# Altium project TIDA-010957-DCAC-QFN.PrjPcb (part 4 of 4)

## Sheet TIDA-010957-DCAC-Power-Tree.SchDoc
size 558 x 431 mm; Date: Not shown in title block; ApprovedBy: Not shown in title block; CheckedBy: Not shown in title block; Author: Not shown in title block; CompanyName: Not shown in title block; Engineer: Not shown in title block; Organization: Not shown in title block; Address1: Not shown in title block; Address2: Not shown in title block; Address3: Not shown in title block; Address4: Not shown in title block; DocumentNumber: 1; Revision: Use project parameter SCH_Rev; SheetNumber: 11; SheetTotal: 12; PageSetup: Record=PageOptions¦CenterHorizontal=True¦CenterVertical=True¦PrintScale=1.00¦XCorrection=1.00¦YCorrection=1.00¦PrintKind=0¦BorderSize=5000000¦LeftOffset=0¦BottomOffset=0¦Orientation=2¦PaperLength=1000¦PaperWidth=1000¦Scale=100¦PaperSource=15¦PrintQuality=600¦MediaType=1¦DitherType=10¦PaperKind=Letter¦PrintScaleMode=1
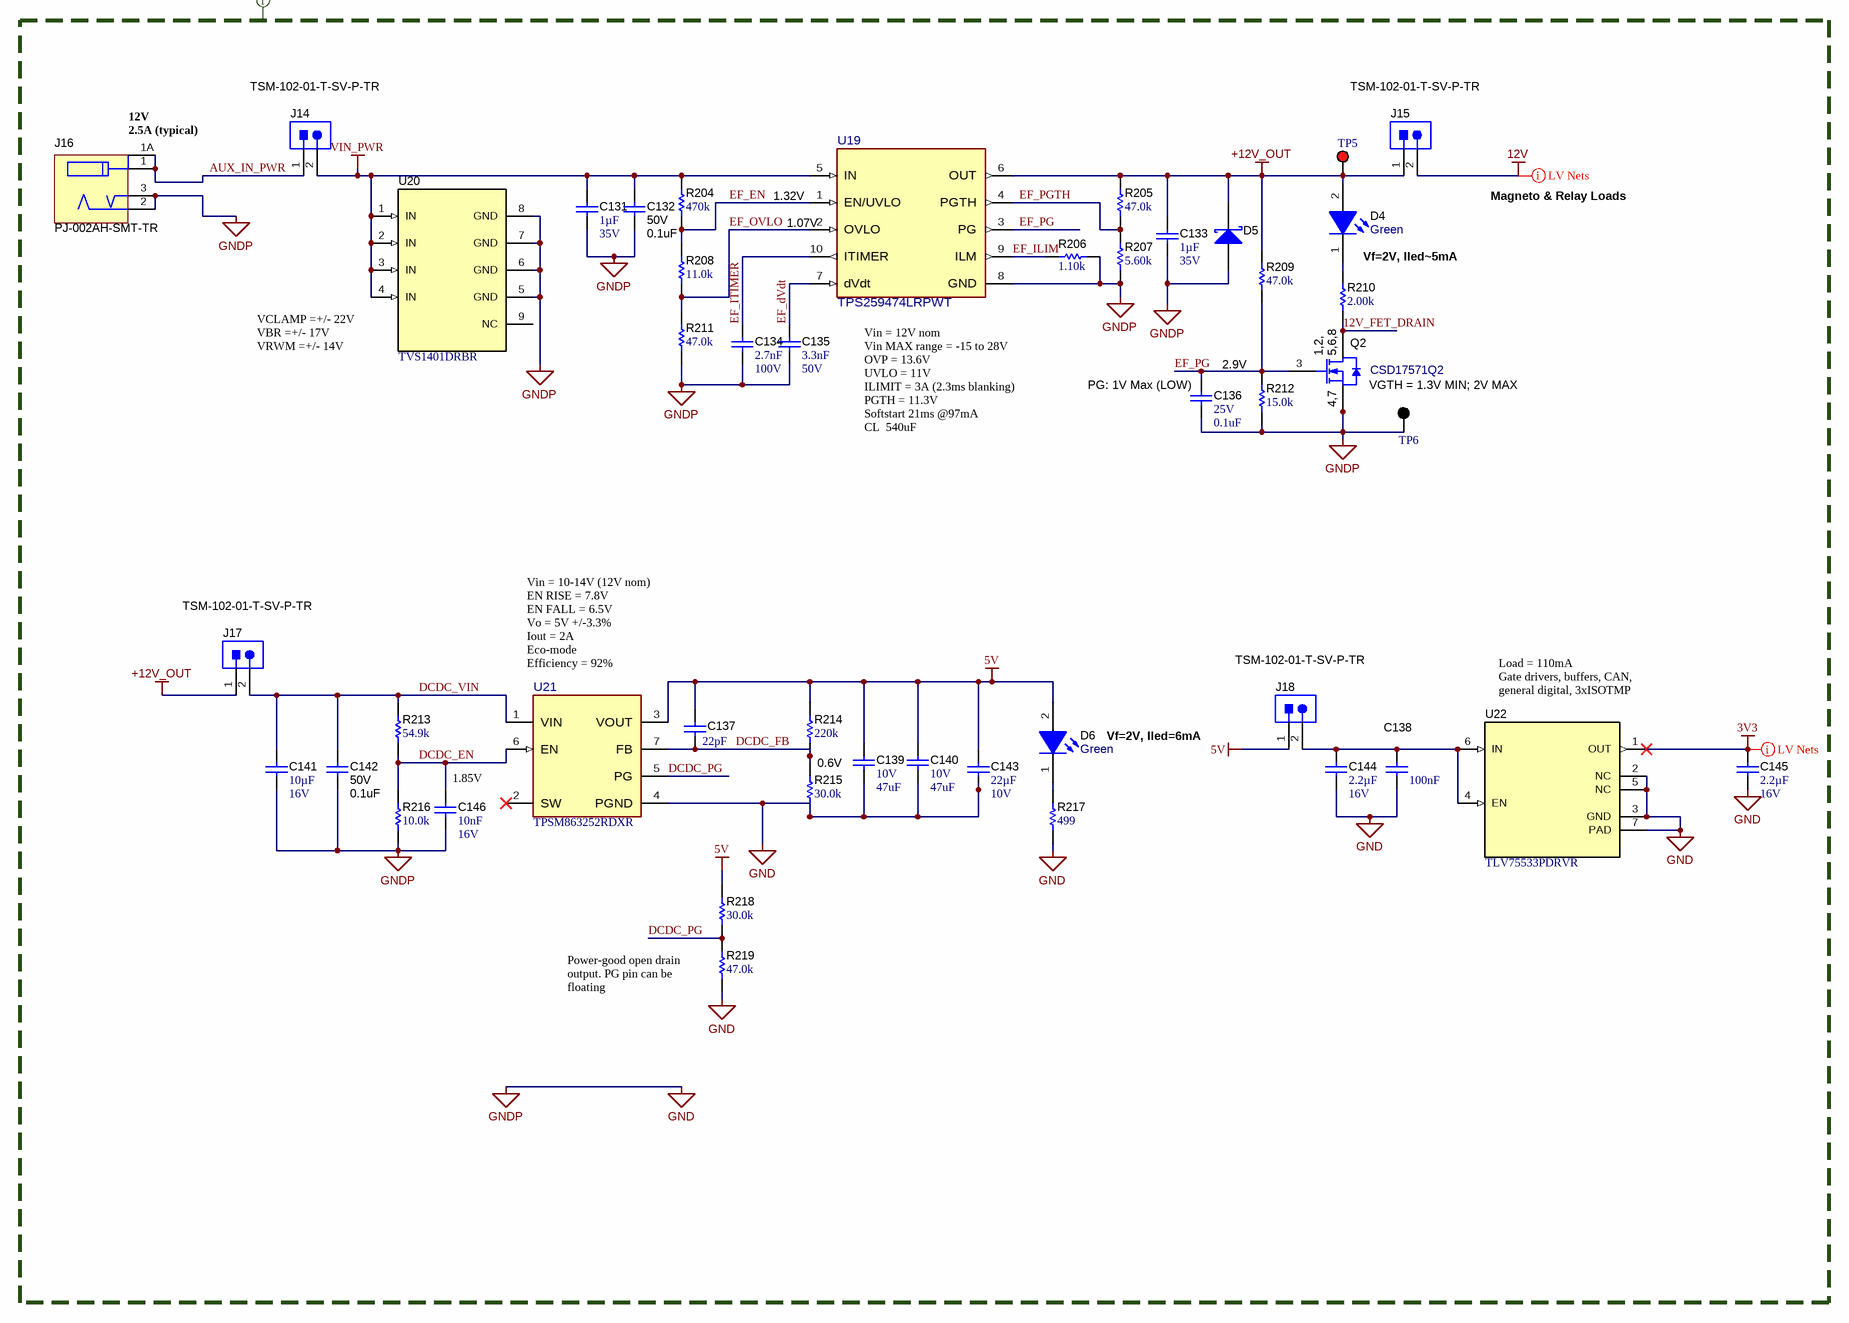
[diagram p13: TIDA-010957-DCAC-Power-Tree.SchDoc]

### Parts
C131  Cap_F: 1µF  VDC_V: 35V  [0603]  (hidden comment: C1608X7R1V105K080AC)
C132  VDC_V: 50V  ValueDisplayed: 0.1uF  [0402S]  (hidden comment: GCM155R71H104KE02D)
C133  Cap_F: 1µF  VDC_V: 35V  [0603]  (hidden comment: C1608X7R1V105K080AC)
C134  Cap_F: 2.7nF  VDC_V: 100V  [0603]  (hidden comment: GRM188R72A272KA01D)
C135  Cap_F: 3.3nF  VDC_V: 50V  [0603]  (hidden comment: C0603X332K5RACTU)
C136  VDC_V: 25V  ValueDisplayed: 0.1uF  [0402L]  (hidden comment: GRM155R71E104KE14D)
C137  ValueDisplayed: 22pF  [0603]  (hidden comment: GRM1885C2A220JA01D)
C138  Cap_F: 100nF  [0603]  (hidden comment: 06033C104JAT2A)
C139  VDC_V: 10V  ValueDisplayed: 47uF  [1210_270]  (hidden comment: GRM32ER71A476KE15L)
C140  VDC_V: 10V  ValueDisplayed: 47uF  [1210_270]  (hidden comment: GRM32ER71A476KE15L)
C141  Cap_F: 10µF  VDC_V: 16V  [0805_HV]  (hidden comment: EMK212BB7106KG-T)
C142  VDC_V: 50V  ValueDisplayed: 0.1uF  [0402L]  (hidden comment: GCM155R71H104KE02D)
C143  Cap_F: 22µF  VDC_V: 10V  [0805_HV]  (hidden comment: GRM21BZ71A226ME15L)
C144  Cap_F: 2.2µF  VDC_V: 16V  [0603]  (hidden comment: EMK107BB7225KA-T)
C145  Cap_F: 2.2µF  VDC_V: 16V  [0603]  (hidden comment: EMK107BB7225KA-T)
C146  Cap_F: 10nF  VDC_V: 16V  [0603]  (hidden comment: C0603C103K4RACTU)
D4  value Green  [WL-SMCW_GREEN]  (hidden comment: 150060VS75000)
D5  B330A-13-F  [SMA]  (value not drawn)
D6  value Green  [WL-SMCW_GREEN]  (hidden comment: 150060VS75000)
J14  TSM-102-01-T-SV-P-TR  [Samtec_TSM-102-01-T-SV-P-TR]
J15  TSM-102-01-T-SV-P-TR  [Samtec_TSM-102-01-T-SV-P-TR]
J16  PJ-002AH-SMT-TR  [CUI_PJ-002AH-SMT]
J17  TSM-102-01-T-SV-P-TR  [Samtec_TSM-102-01-T-SV-P-TR]
J18  TSM-102-01-T-SV-P-TR  [Samtec_TSM-102-01-T-SV-P-TR]
Q2  CSD17571Q2  [DQK0006C]
R204  ValueDisplayed: 470k  [0603]  (hidden comment: RC0603FR-07470KL)
R205  ValueDisplayed: 47.0k  [0603]  (hidden comment: RC0603FR-0747KL)
R206  ValueDisplayed: 1.10k  [0603]  (hidden comment: RC0603FR-071K1L)
R207  ValueDisplayed: 5.60k  [0603]  (hidden comment: RC0603FR-075K6L)
R208  ValueDisplayed: 11.0k  [0603]  (hidden comment: RC0603FR-0711KL)
R209  ValueDisplayed: 47.0k  [0603]  (hidden comment: RC0603FR-0747KL)
R210  ValueDisplayed: 2.00k  [0603]  (hidden comment: RC0603FR-072KL)
R211  ValueDisplayed: 47.0k  [0603]  (hidden comment: RC0603FR-0747KL)
R212  ValueDisplayed: 15.0k  [0603]  (hidden comment: RC0603FR-0715KL)
R213  ValueDisplayed: 54.9k  [0603]  (hidden comment: RC0603FR-0754K9L)
R214  ValueDisplayed: 220k  [0603]  (hidden comment: RC0603FR-07220KL)
R215  ValueDisplayed: 30.0k  [0603]  (hidden comment: RC0603FR-0730KL)
R216  ValueDisplayed: 10.0k  [0603]  (hidden comment: RG1608P-103-B-T5)
R217  ValueDisplayed: 499  [0603]  (hidden comment: CRCW0603499RFKEAC)
R218  ValueDisplayed: 30.0k  [0603]  (hidden comment: RC0603FR-0730KL)
R219  ValueDisplayed: 47.0k  [0603]  (hidden comment: RC0603FR-0747KL)
TP5  5010  [Keystone5010]  (value not drawn)
TP6  5011  [Keystone5011]  (value not drawn)
U19  TPS259474LRPWT  [RPW0010A-MFG]
U20  TVS1401DRBR  [DRB0008A]
U21  TPSM863252RDXR  [RDX0007A-MFG]
U22  TLV75533PDRVR  [DRV0006A]

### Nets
3V3: C145.1 U22.1(OUT)
5V: C137.1 C139.1 C140.1 C143.1 D6.2(A) J18.1 R214.2 R218.2 U21.3(VOUT)
12V: J15.2
+12V_OUT: C133.1 D4.2(A) D5.1(K) J15.1 J17.1 R205.2 R209.2 TP5.1 U19.6(OUT)
GND: C131.2 C132.2 C133.2 C134.2 C135.2 C136.2 C138.2 C139.2 C140.2 C141.2 C142.1 C143.2 C144.2 C145.2 C146.2 D5.2(A) J16.2 J16.3 Q2.4(S) Q2.7(S) R206.1 R207.1 R211.1 R212.1 R215.1 R216.2 R217.1 R219.1 TP6.1 U19.8(GND) U20.5(GND) U20.6(GND) U20.7(GND) U20.8(GND) U21.4(PGND) U22.2(NC) U22.3(GND) U22.5(NC) U22.7(PAD)  [also labelled GNDP]
VIN_PWR: C131.1 C132.1 J14.2 R204.2 U19.5(IN) U20.1(IN) U20.2(IN) U20.3(IN) U20.4(IN)
12V_FET_DRAIN: Q2.1(D) Q2.2(D) Q2.5(D) Q2.6(D) Q2.8(D) R210.1
AUX_IN_PWR: J14.1 J16.1 J16.1A
DCDC_EN: C146.1 R213.1 R216.1 U21.6(EN)
DCDC_FB: C137.2 R214.1 R215.2 U21.7(FB)
DCDC_PG: R218.1 R219.2 U21.5(PG)
DCDC_VIN: C141.1 C142.2 J17.2 R213.2 U21.1(VIN)
EF_dVdt: C135.1 U19.7(dVdt)
EF_EN: R204.1 R208.2 U19.1(EN/UVLO)
EF_ILIM: R206.2 U19.9(ILM)
EF_ITIMER: C134.1 U19.10(ITIMER)
EF_OVLO: R208.1 R211.2 U19.2(OVLO)
EF_PG: C136.1 Q2.3(G) R209.1 R212.2 U19.3(PG)
EF_PGTH: R205.1 R207.2 U19.4(PGTH)
NetC138_1: C138.1 C144.1 J18.2 U22.4(EN) U22.6(IN)
NetD4_1: D4.1(K) R210.2
NetD6_1: D6.1(K) R217.2

Not connected (* = marked no-connect by the designer): U20 9(NC); U21 2(SW)*

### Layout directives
net class LV Nets: 3V3, 12V
net class LV_NET: 3V3, 5V, 12V, 12V_FET_DRAIN, +12V_OUT, AUX_IN_PWR, DCDC_EN, DCDC_FB, DCDC_PG, DCDC_VIN, EF_dVdt, EF_EN, EF_ILIM, EF_ITIMER, EF_OVLO, EF_PG, EF_PGTH, GND, GNDP, VIN_PWR

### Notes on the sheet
- (near J16) 12V
  2.5A (typical)
- (near U19) 1.32V
- Magneto & Relay Loads
- (near U19) 1.07V
- Vf=2V, Iled~5mA
- (near U20) VCLAMP =+/- 22V
  VBR =+/- 17V
  VRWM =+/- 14V
- (near C136) PG: 1V Max (LOW)
- 2.9V
- VGTH = 1.3V MIN; 2V MAX
- (near U19) Vin = 12V nom
  Vin MAX range = -15 to 28V
  OVP = 13.6V
  UVLO = 11V
  ILIMIT = 3A (2.3ms blanking)
  PGTH = 11.3V
  Softstart 21ms @97mA
  CL  540uF
- Vin = 10-14V (12V nom)
  EN RISE = 7.8V
  EN FALL = 6.5V
  Vo = 5V +/-3.3%
  Iout = 2A
  Eco-mode
  Efficiency = 92%
- Vf=2V, Iled=6mA
- (near U22) Load = 110mA
  Gate drivers, buffers, CAN, general digital, 3xISOTMP
- (near C146) 1.85V
- 0.6V
- Power-good open drain output. PG pin can be floating

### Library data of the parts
C131 C133 = CMP-0007052-4: CAP, CERM, 1 uF, 35 V, +/- 10%, X7R, 0603; Manufacturer: TDK; TaMin_C: -55°C; Polarized: N; SizeAreaWB_mm2: 4.68; Value1: Unknown; U/M: EA; Value: 1uF; TaMax_C: 125°C; SizeZ_mm: 1; SizeX_mm: 1.6; SizeY_mm: 0.8; SizeArea_mm2: 1.28; AEC Category: Q200
C132 C142 = CMP-0006356-2: CAP, CERM, 0.1 uF, 50 V, +/- 10%, X7R, AEC-Q200 Grade 1, 0402; Manufacturer: MuRata; TaMin_C: -55°C; Polarized: N; SizeAreaWB_mm2: 3; Value1: Unknown; U/M: EA; Value: 0.1uF; TaMax_C: 125°C; SizeZ_mm: 0.6; SizeX_mm: 1; SizeY_mm: 0.5; Cap_Case: 0402; AEC Qualified: Y; Cap_F: 100nF; AEC Category: Q200
C134 = CMP-0007477-4: CAP, CERM, 2700 pF, 100 V, +/- 10%, X7R, 0603; Manufacturer: MuRata; TaMin_C: -55°C; Polarized: N; SizeAreaWB_mm2: 4.68; Value1: Unknown; U/M: EA; Value: 2700pF; TaMax_C: 125°C; SizeZ_mm: 1; SizeX_mm: 1.6; SizeY_mm: 0.8; SizeArea_mm2: 1.28; AEC Category: Q200
C135 = CMP-0006985-4: CAP, CERM, 3300 pF, 50 V, +/- 10%, X7R, 0603; Manufacturer: Kemet; TaMin_C: -55°C; Polarized: N; SizeAreaWB_mm2: 4.68; Value1: Unknown; U/M: EA; Value: 3300pF; TaMax_C: 125°C; SizeZ_mm: 1; SizeX_mm: 1.6; SizeY_mm: 0.8; SizeArea_mm2: 1.28; AEC Category: Q200
C136 = CMP-0006659-2: CAP, CERM, 0.1 uF, 25 V, +/- 10%, X7R, 0402; Manufacturer: MuRata; TaMin_C: -55°C; Polarized: N; SizeAreaWB_mm2: 3; Value1: Unknown; U/M: EA; Value: 0.1uF; TaMax_C: 125°C; SizeZ_mm: 0.6; SizeX_mm: 1; SizeY_mm: 0.5; Cap_Case: 0402; Cap_F: 100nF; AEC Category: Q200
C137 = CMP-0007255-4: CAP, CERM, 22 pF, 100 V, +/- 5%, C0G/NP0, 0603; Manufacturer: MuRata; TaMin_C: -55°C; Polarized: N; SizeAreaWB_mm2: 4.68; Value1: Unknown; U/M: EA; Value: 22pF; TaMax_C: 125°C; SizeZ_mm: 1; SizeX_mm: 1.6; SizeY_mm: 0.8; Value2: 100V; SizeArea_mm2: 1.28; AEC Category: Q200
C138 = CMP-0006752-5: CAP, CERM, 0.1 uF, 25 V, +/- 5%, X7R, 0603; Manufacturer: AVX; TaMin_C: -55°C; ESR_ohm: 0.05; Polarized: N; SizeAreaWB_mm2: 4.68; Value1: 0.05 ohm; U/M: EA; Value: 0.1uF; TaMax_C: 125°C; SizeZ_mm: 1; SizeX_mm: 1.6; SizeY_mm: 0.8; Value2: 25V; SizeArea_mm2: 1.28; AEC Category: Q200
C139 C140 = CMP-0009220-2: CAP, CERM, 47 uF, 10 V, +/- 10%, X7R, 1210; Manufacturer: MuRata; TaMin_C: -55°C; Polarized: N; SizeAreaWB_mm2: 14.7; Value1: Unknown; U/M: EA; Value: 47uF; TaMax_C: 125°C; SizeZ_mm: 2.7; SizeX_mm: 3.2; SizeY_mm: 2.5; Cap_Case: 1210; SizeArea_mm2: 8; Cap_F: 47µF; AEC Category: Q200
C141 = CMP-0085283-1: CAP, CERM, 10 µF, 16 V,+/- 10%, X7R, 0805; Manufacturer: Taiyo Yuden; TaMin_C: -55°C; AEC Qualified: N; U/M: EA; TaMax_C: 125°C; SizeAreaWB_mm2: 6.75; SizeZ_mm: 1.45; Value: 10uF; SizeY_mm: 1.25; SizeArea_mm2: 2.5; AEC Category: Q200; SizeX_mm: 2; Cap_Case: 0805
C143 = CMP-0008377-2: CAP, CERM, 22 uF, 10 V, +/- 20%, X7R, 0805; Manufacturer: MuRata; SizeY_mm: 1.25; Cap_Case: 0805; SizeArea_mm2: 2.5; AEC Qualified: N; AEC Category: Q200; ValueDisplayed: 22uF; TaMin_C: -55°C; SizeAreaWB_mm2: 6.75; Value1: Unknown; U/M: EA; Value: 22uF; TaMax_C: 125°C; SizeZ_mm: 1.45; SizeX_mm: 2
C144 C145 = CMP-0007121-4: CAP, CERM, 2.2 uF, 16 V, +/- 10%, X7R, 0603; Manufacturer: Taiyo Yuden; TaMin_C: -55°C; Polarized: N; SizeAreaWB_mm2: 4.68; Value1: Unknown; U/M: EA; Value: 2.2uF; TaMax_C: 125°C; SizeZ_mm: 1; SizeX_mm: 1.6; SizeY_mm: 0.8; SizeArea_mm2: 1.28; AEC Category: Q200
C146 = CMP-0006853-4: CAP, CERM, 0.01 uF, 16 V, +/- 10%, X7R, 0603; Manufacturer: Kemet; TaMin_C: -55°C; Polarized: N; SizeAreaWB_mm2: 4.68; Value1: Unknown; U/M: EA; Value: 0.01uF; TaMax_C: 125°C; SizeZ_mm: 1; SizeX_mm: 1.6; SizeY_mm: 0.8; SizeArea_mm2: 1.28; AEC Category: Q200
D4 D6 = CMP-0002894-2: LED, Green, SMD; Manufacturer: Wurth Elektronik; Type: AlInGaP; Value2: 2V; Io_A: 20mA; Value1: W
D5 = CMP-0028350-2: Diode, Schottky, 30 V, 3 A, SMA; Manufacturer: Diodes Inc.; Io_A: 3A; SizeZ_mm: 2.87; SizeAreaWB_mm2: 37.3428; Value: 30V; TJmax_C: 125°C; Green_Lifecycle: Active; SizeY_mm: 2.92; Vf_V: 500mV; Green_REACh: Passed; SizeArea_mm2: 16.3228; AEC Category: Q101; Value2: 0.5V; SizeX_mm: 5.59; RJC_CperW: 25
J14 J15 J17 J18 = CMP-0075491-1: Header, 100mil, 2x1, Tin, SMD; Manufacturer: Samtec; Pitch_mm: 2.54; Gender: Male; Cert_CSA: Y; Current_A: 5.4A; Voltage_V: 475V; CT: False; Shrouded: N; Row_Count: 1; CNHeader: True
J16 = CMP-0075012-1: Power Jack, SMT; Manufacturer: CUI Inc.; Green_Lifecycle: Not Set; Green_REACh: Incomplete; CNHeader: False
Q2 = CMP-0000585-1: MOSFET, N-CH, 30 V, 22 A, DQK0006C (WSON-6); Alternate Manufacturer: None; Manufacturer: Texas Instruments; SizeZ_mm: 0.8; ChType: N; Value2: 2.4 nC; Value1: 0.02; VdsMax_V: 30V; SizeX_mm: 2; Vgs_V: 20V; Value: 30V; Rdson45_ohm: 0.029; SizeArea_mm2: 4; AEC Category: Q101; IdsMax_A: 22A; SizeAreaWB_mm2: 9; U/M: EA; QgTyp_nC: 2.4
R204 = CMP-0023128-4: RES, 470 k, 1%, 0.1 W, 0603; Manufacturer: Yageo; Power_W: 100mW; TempCo: 100 ppm/C; Value: 470k; SizeX_mm: 1.6; SizeY_mm: 0.8; SizeZ_mm: 1; Value2: 0.1W; SizeArea_mm2: 1.28; AEC Qualified: N; VDC_V: 75V; AEC Category: Q200; SizeAreaWB_mm2: 4.68
R205 R209 R211 R219 = CMP-0023133-5: RES, 47.0 k, 1%, 0.1 W, 0603; Manufacturer: Yageo; Power_W: 100mW; TempCo: 100 ppm/C; Value_Code: 47k0; Value: 47.0k; Res_ohm: 47k; SizeX_mm: 1.6; SizeY_mm: 0.8; SizeZ_mm: 1; Value2: 0.1W; SizeArea_mm2: 1.28; AEC Qualified: N; VDC_V: 75V; AEC Category: Q200; SizeAreaWB_mm2: 4.68
R206 = CMP-0022870-5: RES, 1.10 k, 1%, 0.1 W, 0603; Manufacturer: Yageo; Power_W: 100mW; TempCo: 100 ppm/C; Value_Code: 1k10; Value: 1.10k; EIA_Code: E96; Res_ohm: 1.1k; SizeX_mm: 1.6; SizeY_mm: 0.8; SizeZ_mm: 1; Value2: 0.1W; SizeArea_mm2: 1.28; AEC Qualified: N; VDC_V: 75V; AEC Category: Q200; SizeAreaWB_mm2: 4.68
R207 = CMP-0023203-5: RES, 5.60 k, 1%, 0.1 W, 0603; Manufacturer: Yageo; Power_W: 100mW; TempCo: 100 ppm/C; Value_Code: 5k60; Value: 5.60k; Res_ohm: 5.6k; SizeX_mm: 1.6; SizeY_mm: 0.8; SizeZ_mm: 1; Value2: 0.1W; SizeArea_mm2: 1.28; AEC Qualified: N; VDC_V: 75V; AEC Category: Q200; SizeAreaWB_mm2: 4.68
R208 = CMP-0022763-5: RES, 11.0 k, 1%, 0.1 W, 0603; Manufacturer: Yageo; Power_W: 100mW; TempCo: 100 ppm/C; Value_Code: 11k0; Value: 11.0k; EIA_Code: E96; Res_ohm: 11k; SizeX_mm: 1.6; SizeY_mm: 0.8; SizeZ_mm: 1; Value2: 0.1W; SizeArea_mm2: 1.28; AEC Qualified: N; VDC_V: 75V; AEC Category: Q200; SizeAreaWB_mm2: 4.68
R210 = CMP-0023000-5: RES, 2.00 k, 1%, 0.1 W, 0603; Manufacturer: Yageo; Power_W: 100mW; TempCo: 100 ppm/C; Value_Code: 2k00; Value: 2.00k; EIA_Code: E96; Res_ohm: 2k; SizeX_mm: 1.6; SizeY_mm: 0.8; SizeZ_mm: 1; Value2: 0.1W; SizeArea_mm2: 1.28; AEC Qualified: N; VDC_V: 75V; AEC Category: Q200; SizeAreaWB_mm2: 4.68
R212 = CMP-0022816-5: RES, 15.0 k, 1%, 0.1 W, 0603; Manufacturer: Yageo; Power_W: 100mW; TempCo: 100 ppm/C; Value_Code: 15k0; Value: 15.0k; EIA_Code: E96; Res_ohm: 15k; SizeX_mm: 1.6; SizeY_mm: 0.8; SizeZ_mm: 1; Value2: 0.1W; SizeArea_mm2: 1.28; AEC Qualified: N; VDC_V: 75V; AEC Category: Q200; SizeAreaWB_mm2: 4.68
R213 = CMP-0023180-5: RES, 54.9 k, 1%, 0.1 W, 0603; Manufacturer: Yageo; Power_W: 100mW; TempCo: 100 ppm/C; Value_Code: 54k9; Value: 54.9k; EIA_Code: E96; SizeX_mm: 1.6; SizeY_mm: 0.8; SizeZ_mm: 1; Value2: 0.1W; SizeArea_mm2: 1.28; AEC Qualified: N; VDC_V: 75V; AEC Category: Q200; SizeAreaWB_mm2: 4.68
R214 = CMP-0022917-4: RES, 220 k, 1%, 0.1 W, 0603; Manufacturer: Yageo; Power_W: 100mW; TempCo: 100 ppm/C; Value: 220k; SizeX_mm: 1.6; SizeY_mm: 0.8; SizeZ_mm: 1; Value2: 0.1W; SizeArea_mm2: 1.28; AEC Qualified: N; VDC_V: 75V; AEC Category: Q200; SizeAreaWB_mm2: 4.68
R215 R218 = CMP-0023020-5: RES, 30.0 k, 1%, 0.1 W, 0603; Manufacturer: Yageo; Power_W: 100mW; TempCo: 100 ppm/C; Value_Code: 30k0; Value: 30.0k; Res_ohm: 30k; SizeX_mm: 1.6; SizeY_mm: 0.8; SizeZ_mm: 1; Value2: 0.1W; SizeArea_mm2: 1.28; AEC Qualified: N; VDC_V: 75V; AEC Category: Q200; SizeAreaWB_mm2: 4.68
R216 = CMP-0023404-3: RES, 10.0 k, 0.1%, 0.1 W, 0603; Manufacturer: Susumu Co Ltd; Power_W: 100mW; TempCo: 25 ppm/C; Value_Code: 10k0; U/M: EA; Value: 10.0k; EIA_Code: E192; Res_ohm: 10k; SizeX_mm: 1.6; SizeY_mm: 0.8; SizeZ_mm: 1; Value2: 0.1W; SizeArea_mm2: 1.28; VDC_V: 75V; AEC Category: Q200
R217 = CMP-0082532-1: RES, 499, 1%, 0.1 W, 0603; Manufacturer: Vishay-Dale; Power_W: 100mW; TempCo: 100 ppm/C; SizeAreaWB_mm2: 4.68; Value_Code: 499R; Value: 499; EIA_Code: E96; SizeX_mm: 1.6; SizeY_mm: 0.8; SizeZ_mm: 1; Value2: 0.1W; SizeArea_mm2: 1.28; AEC Qualified: N; VDC_V: 75V; AEC Category: Q200
TP5 = CMP-0055147-2: Test Point, Multipurpose, Red, TH; Manufacturer: Keystone Electronics; CT: TRUE; ContactFinish: Silver; Green_Lifecycle: Active; CNHeader: FALSE; Green_REACh: Passed
TP6 = CMP-0055148-2: Test Point, Multipurpose, Black, TH; Manufacturer: Keystone Electronics; CNHeader: FALSE; ContactFinish: Silver; Green_REACh: Passed; Green_Lifecycle: Active; CT: TRUE
U19 = CMP-0088329-1: 2.7- 23V, 5.5 A, 28 mΩ Reverse Current Blocking eFuse with Input Reverse Polarity Protection; Manufacturer: Texas Instruments; AEC Qualified: No; Nominal Supply Current: 0.5-6A; Threshold Voltage: 1.2/1.1V; Standoff Height: 0mm; Number Of Rails Monitored: 1; SizeZ_mm: 1mm; Min Supply Voltage: 2.7V; Reset Type: Active Low; TJmax_C: +125°C; Output Voltage: 42V
U20 = CMP-0083940-3: 14 V Bidirectional Flat-Clamp Surge Protection Device, DRB0008A (VSON-8); Alternate PartNumber: TVS1401DRBT; Alternate Manufacturer: Texas Instruments; CompType: IC; SizeAreaWB_mm2: 16.0; SizeZ_mm: 1.0; SizeY_mm: 3.0; AEC Category: Q200; SizeArea_mm2: 9.0; AEC Qualified: N
U21 = CMP-0034908-2: 3V to 16 V Input, 3-A Synchronous Step-Down Voltage Regulator Module, QFN-FCMOD7; Manufacturer: Texas Instruments; SizeZ_mm: 2.1mm; AEC Qualified: No; Max Duty Cycle: 95%; Max Supply Voltage: 17V; Nominal Supply Current: 100-400uA; Number Of Outputs: 1; Output Type: AdjustableProgrammable; Output Voltage: 0.6-10V; Standoff Height: 0mm; Switching Frequency: 1.2MHz; Switching Topology: Buck; TJmax_C: +125°C; AEC Category: Q200; CompType: IC
U22 = CMP-0013427-7: 500mA LDO, DRV0006A (WSON-6); Manufacturer: Texas Instruments; SizeX_mm: 2; CompType: IC; SizeZ_mm: 0.8; SizeArea_mm2: 4; SizeAreaWB_mm2: 9; U/M: EA

## Sheet TIDA-010957-DCAC-Mechanics.SchDoc
size 431 x 279 mm; Date: Not shown in title block; ApprovedBy: Not shown in title block; CheckedBy: Not shown in title block; Author: Not shown in title block; CompanyName: Not shown in title block; Engineer: Not shown in title block; Organization: Not shown in title block; Address1: Not shown in title block; Address2: Not shown in title block; Address3: Not shown in title block; Address4: Not shown in title block; DocumentNumber: 3; Revision: Use project parameter SCH_Rev; SheetNumber: 2; SheetTotal: 12; PageSetup: Record=PageOptions¦CenterHorizontal=True¦CenterVertical=True¦PrintScale=1.00¦XCorrection=1.00¦YCorrection=1.00¦PrintKind=0¦BorderSize=5000000¦LeftOffset=0¦BottomOffset=0¦Orientation=2¦PaperLength=1000¦PaperWidth=1000¦Scale=100¦PaperSource=15¦PrintQuality=600¦MediaType=1¦DitherType=10¦PaperKind=Letter¦PrintScaleMode=1
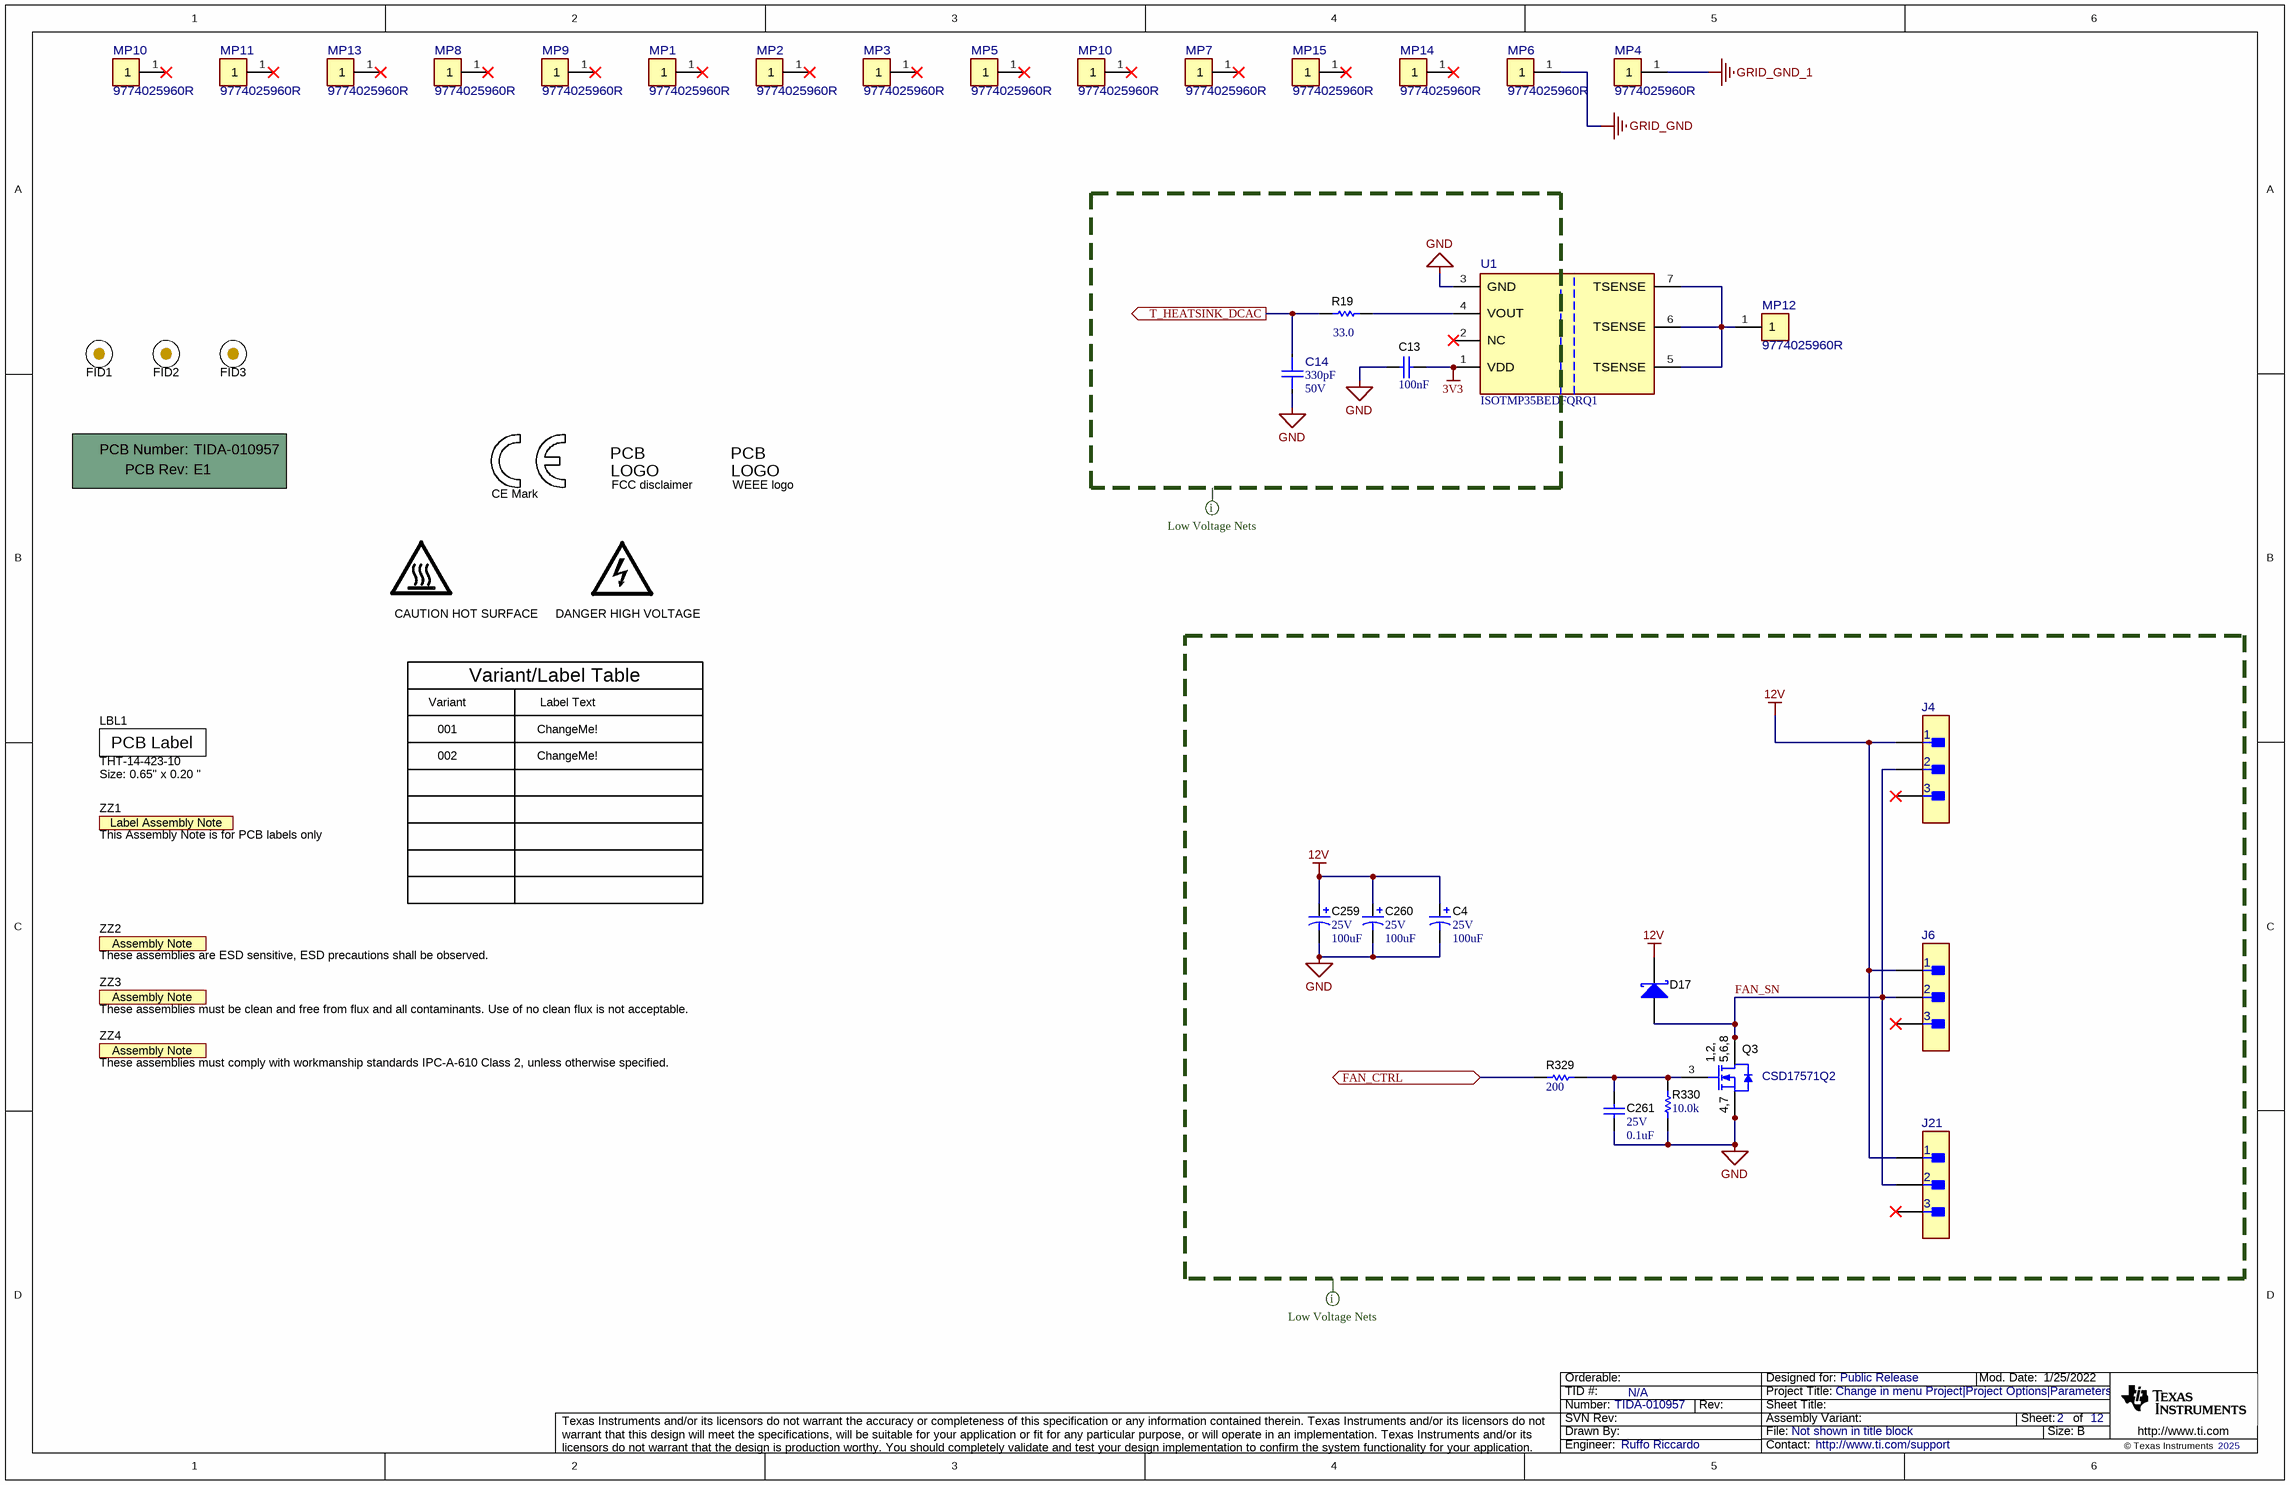
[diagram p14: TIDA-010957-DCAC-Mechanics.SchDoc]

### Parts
(Parts that share a designator on the sheet are numbered #1, #2 ... from top to bottom, then left to right.)
!PCB1  Printed Circuit Board  (value not drawn)  (mechanical)
C4  VDC_V: 25V  ValueDisplayed: 100uF  [FM_630x1120]  (hidden comment: EEU-FM1E101)
C13  Cap_F: 100nF  [0603]  (hidden comment: 06033C104JAT2A)
C14  ValueDisplayed: 330pF  VDC_V: 50V  [FP-CGA3E2C0G1H331J080AA_0603-MFG]  (hidden comment: CGA3E2C0G1H331J080AA)
C259  VDC_V: 25V  ValueDisplayed: 100uF  [FM_630x1120]  (hidden comment: EEU-FM1E101)
C260  VDC_V: 25V  ValueDisplayed: 100uF  [FM_630x1120]  (hidden comment: EEU-FM1E101)
C261  VDC_V: 25V  ValueDisplayed: 0.1uF  [0402L]  (hidden comment: GRM155R71E104KE14D)
D17  B160-13-F  [SMA]  (value not drawn)
FID1  Fiducial  [Fiducial10-20]  (value not drawn)
FID2  Fiducial  [Fiducial10-20]  (value not drawn)
FID3  Fiducial  [Fiducial10-20]  (value not drawn)
J4  0022111031  [FP-0022111031_HDR3-MFG]  (value not drawn)
J6  0022111031  [FP-0022111031_HDR3-MFG]  (value not drawn)
J21  0022111031  [FP-0022111031_HDR3-MFG]  (value not drawn)
LBL1  THT-14-423-10  Note: Size: 0.65" x 0.20 "  [Label_650x200]
Logo1  CE Mark  [CE_Mark_5mm]  (no BOM)
Logo3  FCC disclaimer  [FCC_disclaimer]  (no BOM)
Logo4  WEEE logo  [WEEE_Minimum]  (no BOM)
LOGO5  CAUTION HOT SURFACE  [IEC_HotSurface_Small]  (no BOM)
LOGO6  DANGER HIGH VOLTAGE  [IEC_HighVoltage_Small]  (no BOM)
MP1  9774025960R  [FP-9774025960R_STAND_OFF-MFG]
MP2  9774025960R  [FP-9774025960R_STAND_OFF-MFG]
MP3  9774025960R  [FP-9774025960R_STAND_OFF-MFG]
MP4  9774025960R  [FP-9774025960R_STAND_OFF-MFG]
MP5  9774025960R  [FP-9774025960R_STAND_OFF-MFG]
MP6  9774025960R  [FP-9774025960R_STAND_OFF-MFG]
MP7  9774025960R  [FP-9774025960R_STAND_OFF-MFG]
MP8  9774025960R  [FP-9774025960R_STAND_OFF-MFG]
MP9  9774025960R  [FP-9774025960R_STAND_OFF-MFG]
MP10#1  9774025960R  [FP-9774025960R_STAND_OFF-MFG]
MP10#2  9774025960R  [FP-9774025960R_STAND_OFF-MFG]
MP11  9774025960R  [FP-9774025960R_STAND_OFF-MFG]
MP12  9774025960R  [FP-9774025960R_STAND_OFF-MFG]
MP13  9774025960R  [FP-9774025960R_STAND_OFF-MFG]
MP14  9774025960R  [FP-9774025960R_STAND_OFF-MFG]
MP15  9774025960R  [FP-9774025960R_STAND_OFF-MFG]
Q3  CSD17571Q2  [DQK0006C]
R19  ValueDisplayed: 33.0  [0402L]  (hidden comment: ERJ-2RKF33R0X)
R329  ValueDisplayed: 200  [0402L]  (hidden comment: CRCW0402200RJNED)
R330  ValueDisplayed: 10.0k  [0402L]  (hidden comment: CRCW040210K0FKED)
U1  ISOTMP35BEDFQRQ1  [DFQ0007A-MFG]
ZZ1  This Assembly Note is for PCB labels only  [AssemblyNoteLabel]  (no BOM)
ZZ2  These assemblies are ESD sensitive, ESD precautions shall be observed.  [AssemblyNote]  (no BOM)
ZZ3  These assemblies must be clean and free from flux and all contaminants. Use of no clean flux is not acceptable.  [AssemblyNote]  (no BOM)
ZZ4  These assemblies must comply with workmanship standards IPC-A-610 Class 2, unless otherwise specified.  [AssemblyNote]  (no BOM)

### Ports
FAN_CTRL (bidir), T_HEATSINK_DCAC (out)

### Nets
3V3: C13.1 U1.1(VDD)
12V: C4.1(+) C259.1(+) C260.1(+) D17.1(K) J4.1 J6.1 J21.1
GND: C4.2(-) C13.2 C14.2 C259.2(-) C260.2(-) C261.2 Q3.4(S) Q3.7(S) R330.1 U1.3(GND)
GRID_GND: MP6.1
GRID_GND_1: MP4.1
FAN_CTRL: R329.1 ; port FAN_CTRL
FAN_SN: D17.2(A) J4.2 J6.2 J21.2 Q3.1(D) Q3.2(D) Q3.5(D) Q3.6(D) Q3.8(D)
T_HEATSINK_DCAC: C14.1 R19.1 ; port T_HEATSINK_DCAC
NetC261_1: C261.1 Q3.3(G) R329.2 R330.2
NetMP12_1: MP12.1 U1.5(TSENSE) U1.6(TSENSE) U1.7(TSENSE)
NetR19_2: R19.2 U1.4(VOUT)

Not connected (* = marked no-connect by the designer): J4 3*; J6 3*; J21 3*; MP1 1*; MP2 1*; MP3 1*; MP5 1*; MP7 1*; MP8 1*; MP9 1*; MP10#1 1*; MP10#2 1*; MP11 1*; MP13 1*; MP14 1*; MP15 1*; U1 2(NC)*

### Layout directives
net class LV_NET: 3V3, 12V, FAN_SN, GND

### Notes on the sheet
- Variant
- Variant/Label Table
- Label Text
- 001
- 002
- ChangeMe!

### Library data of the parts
!PCB1 = CMP-0003618-2: Manufacturer: Any; PartNumber: TIDA-010957
C4 C259 C260 = CMP-0010339-1: CAP, AL, 100 uF, 25 V, +/- 20%, 0.13 ohm, TH; Manufacturer: Panasonic; TaMin_C: -40°C; ESR_ohm: 0.13; Polarized: Y; SizeAreaWB_mm2: 68.89; U/M: EA; Value: 100uF; TaMax_C: 105°C; SizeZ_mm: 12.7; SizeX_mm: 6.3; Cap_Case: 6.3x11.2; SizeArea_mm2: 39.69; CompType: Capacitor; AEC Qualified: N; Cap_F: 100µF; IRMS_A: 455mA; AEC Category: Q200
C13 = CMP-0006752-5: as C138 on sheet TIDA-010957-DCAC-Power-Tree
C14 = CMP-0095085-1: Cap Ceramic 330pF 50V C0G 5% Pad SMD 0603 +125°C Automotive T/R; Manufacturer: TDK; AEC Qualified: Yes; TempCo: 30ppm/°C; Tolerance_%: 0.05%; AEC Grade: Grade 1; SizeZ_mm: 1.1mm
C261 = CMP-0006659-2: as C136 on sheet TIDA-010957-DCAC-Power-Tree
D17 = CMP-0028389-2: Diode, Schottky, 60 V, 1 A, SMA; Manufacturer: Diodes Inc.; Green_Lifecycle: Not Set; SizeAreaWB_mm2: 37.3428; Green_REACh: Incomplete; TJmax_C: 150°C; AEC Category: Q101; SizeZ_mm: 2.87; RJC_CperW: 20; Io_A: 1A; SizeArea_mm2: 16.3228; Vf_V: 700mV; Value2: 0.7V; SizeY_mm: 2.92; Vr_V: 60V; SizeX_mm: 5.59; Value: 60V
FID1-FID3 = CMP-0077181-1: Fiducial mark.  There is nothing to buy or mount.
J4 J6 J21 = CMP-0122568-1: Mini-Latch™ Wire-to-Board Header, Vertical, with Friction Ramp, 3 Circuits, Gold (Au) Plating; Manufacturer: Molex; ContactFinish: Gold,Nickel; Current_A: 3A; Row_Count: 1; Voltage_V: 250V; AEC Qualified: No; Conn Gender: Male; DUT-Pitch_mm: 2.5mm; SizeZ_mm: 12.1mm
LBL1 = CMP-0003625-1: Thermal Transfer Printable Labels, 0.650" W x 0.200" H - 10,000 per roll; Manufacturer: Brady; CompType: Label
Logo1 = CMP-0074844-1: SymbolCreator: a0412235
Logo3 = CMP-0074847-1: FCC_disclaimer; Library Reference: Logo
Logo4 = CMP-0074769-1
LOGO5 = CMP-0074837-1: IEC 61010-1 Hot Surface Warning; SymbolCreator: a0412235; Lib Reference: IEC_HotSurface
LOGO6 = CMP-0074835-1: IEC 61010-1 High Voltage Warning; SymbolCreator: a0412235; Lib Reference: IEC_HighVoltage
MP1-MP9 MP10#1 MP10#2 MP11-MP15 = CMP-0126499-1: WA-SMST SMT Steel Spacer, Ø3.3 Internal non Stop; Manufacturer: Wurth; AEC Qualified: No; SizeZ_mm: 2.6mm
Q3 = CMP-0000585-1: as Q2 on sheet TIDA-010957-DCAC-Power-Tree
R19 = CMP-0026696-1: RES, 33.0, 1%, 0.1 W, 0402; Manufacturer: Panasonic; Power_W: 100mW; TempCo: 100 ppm/C; Value_Code: 33R0; U/M: EA; Value: 33.0; Res_ohm: 33; SizeX_mm: 1; SizeY_mm: 0.5; SizeZ_mm: 0.6; Value2: 0.1W; VDC_V: 50V; AEC Category: Q200
R329 = CMP-0026874-3: RES, 200, 5%, 0.063 W, AEC-Q200 Grade 0, 0402; Manufacturer: Vishay-Dale; Power_W: 63mW; TempCo: 200 ppm/C; Value_Code: 200R; Value: 200; EIA_Code: E24; SizeX_mm: 1; SizeY_mm: 0.5; SizeZ_mm: 0.6; Value2: 0.063W; AEC Qualified: Y; VDC_V: 50V; AEC Category: Q200; AEC Grade: 0
R330 = CMP-0025958-3: RES, 10.0 k, 1%, 0.063 W, AEC-Q200 Grade 0, 0402; Manufacturer: Vishay-Dale; Power_W: 63mW; TempCo: 100 ppm/C; Value_Code: 10k0; Value: 10.0k; EIA_Code: E96; Res_ohm: 10k; SizeX_mm: 1; SizeY_mm: 0.5; SizeZ_mm: 0.6; Value2: 0.063W; AEC Qualified: Y; VDC_V: 50V; AEC Category: Q200; AEC Grade: 0
U1 = CMP-0122473-1: Automotive ±1.5°C, 3-kVRMS Isolated Temperature Sensor With Analog Output With < 2 Seconds Response Time and 500VRMS Working Voltage; Manufacturer: Texas Instruments; SizeZ_mm: 1.75mm; AEC Qualified: Yes; AEC Grade: Grade 0; Max Supply Voltage: 5.5V; Min Supply Voltage: 2.3V; Operating Supply Current: 10uA; Sensor Output: Analog Voltage; Standoff Height: 0.11mm; TaMax_C: +150°C; TaMin_C: -40°C; TJmax_C: +155°C
ZZ1 = CMP-0003616-3
ZZ2 = CMP-0077236-1
ZZ3 = CMP-0077237-1
ZZ4 = CMP-0077238-1

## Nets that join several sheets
1V65: TIDA-010957-DCAC-CONTROLLER (C5.1 R38.1), TIDA-010957-DCAC-Current-Sensing (8 pins), TIDA-010957-DCAC-DC-Voltage-Measurements (C263.2 R332.1 U12.6)
3V3: TIDA-010957-DCAC-CAN (FB13.1), N (11 pins), TIDA-010957-DCAC-Current-Sensing (5 pins), TIDA-010957-DCAC-Measurements-Voltages-AC (FB7.2 FB8.2 FB9.2), TIDA-010957-DCAC-DC-Voltage-Measurements (C80.2 C81.1 FB16.2 U11.14), TIDA-010957-DCAC-FC-OP-AMP (FB11.1), TIDA-010957-DCAC-PWM-BUFFER (R164.2 R174.2 R175.2 R194.2), TIDA-010957-DCAC-Power-Tree (C145.1 U22.1), TIDA-010957-DCAC-Mechanics (C13.1 U1.1), L1 (11 pins), L2 (11 pins), L3 (11 pins)
5V: TIDA-010957-DCAC-CONTROLLER (FB1.1), TIDA-010957-DCAC-CAN (FB12.1), N (8 pins), TIDA-010957-DCAC-Measurements-Voltages-AC (C79.1 L7.2), TIDA-010957-DCAC-DC-Voltage-Measurements (C93.1 L9.2), TIDA-010957-DCAC-Power-Tree (9 pins), L1 (8 pins), L2 (8 pins), L3 (8 pins)
12V: TIDA-010957-DCAC-EMI-Filter (7 pins), TIDA-010957-DCAC-Power-Tree (J15.2), TIDA-010957-DCAC-Mechanics (7 pins)
GND: TIDA-010957-DCAC-CONTROLLER (37 pins), TIDA-010957-DCAC-CAN (7 pins), N (59 pins), TIDA-010957-DCAC-EMI-Filter (7 pins), TIDA-010957-DCAC-Current-Sensing (26 pins), TIDA-010957-DCAC-Measurements-Voltages-AC (23 pins), TIDA-010957-DCAC-DC-Voltage-Measurements (19 pins), TIDA-010957-DCAC-FC-OP-AMP (13 pins), TIDA-010957-DCAC-PWM-BUFFER (49 pins), TIDA-010957-DCAC-Power-Tree (39 pins), TIDA-010957-DCAC-Mechanics (10 pins), L1 (59 pins), L2 (59 pins), L3 (59 pins)
GND_S4_GaN: TIDA-010957-DCAC-Overview (14 pins), N (46 pins), TIDA-010957-DCAC-DC-Voltage-Measurements (13 pins), L1 (46 pins), L2 (46 pins), L3 (46 pins)
GRID_GND: TIDA-010957-DCAC-Overview (J10.1), TIDA-010957-DCAC-EMI-Filter (R94.1), TIDA-010957-DCAC-Mechanics (MP6.1)
GRID_GND_1: TIDA-010957-DCAC-EMI-Filter (C24.1 C25.1), TIDA-010957-DCAC-Mechanics (MP4.1)
VDC+: TIDA-010957-DCAC-Overview (11 pins), N (16 pins), TIDA-010957-DCAC-DC-Voltage-Measurements (U11.1), L1 (16 pins), L2 (16 pins), L3 (16 pins)
BUFF_EN: TIDA-010957-DCAC-CONTROLLER (R65.1), TIDA-010957-DCAC-PWM-BUFFER (25 pins)
CAN_EN: TIDA-010957-DCAC-CONTROLLER (R88.1), TIDA-010957-DCAC-CAN (R224.1 U23.8)
CAN_RX: TIDA-010957-DCAC-CONTROLLER (R71.1), TIDA-010957-DCAC-CAN (U23.5)
CAN_TX: TIDA-010957-DCAC-CONTROLLER (R84.1), TIDA-010957-DCAC-CAN (U23.3)
EN_AUX_ISO_DCAC: TIDA-010957-DCAC-CONTROLLER (D19.2 R67.1), N (R287_N.2 R298_N.2 R308_N.2 R325_N.2), L1 (R287_L1.2 R298_L1.2 R308_L1.2 R325_L1.2), L2 (R287_L2.2 R298_L2.2 R308_L2.2 R325_L2.2), L3 (R287_L3.2 R298_L3.2 R308_L3.2 R325_L3.2)
FAN_CTRL: TIDA-010957-DCAC-CONTROLLER (R334.2), TIDA-010957-DCAC-Mechanics (R329.1)
GND_S2_GaN: N (58 pins), TIDA-010957-DCAC-EMI-Filter (L6.1 L6.2 L6.3 L6.4)
GND_S2_GaN: TIDA-010957-DCAC-EMI-Filter (L1.1 L1.2 L1.3 L1.4), L1 (58 pins)
GND_S2_GaN: TIDA-010957-DCAC-EMI-Filter (L2.1 L2.2 L2.3 L2.4), L2 (58 pins)
GND_S2_GaN: TIDA-010957-DCAC-EMI-Filter (L5.1 L5.2 L5.3 L5.4), L3 (58 pins)
GRID_RELAYS: TIDA-010957-DCAC-CONTROLLER (R63.1), TIDA-010957-DCAC-EMI-Filter (D20.2 R96.1)
I_PCC_L1+: TIDA-010957-DCAC-EMI-Filter (C17.2 L19.2), TIDA-010957-DCAC-Current-Sensing (U2.1)
I_PCC_L1-: TIDA-010957-DCAC-EMI-Filter (L1.5 L1.6 L1.7 L1.8), TIDA-010957-DCAC-Current-Sensing (U2.2)
I_PCC_L2+: TIDA-010957-DCAC-EMI-Filter (C18.2 L19.4), TIDA-010957-DCAC-Current-Sensing (U4.1)
I_PCC_L2-: TIDA-010957-DCAC-EMI-Filter (L2.5 L2.6 L2.7 L2.8), TIDA-010957-DCAC-Current-Sensing (U4.2)
I_PCC_L3+: TIDA-010957-DCAC-EMI-Filter (C19.2 L19.6), TIDA-010957-DCAC-Current-Sensing (U5.1)
I_PCC_L3-: TIDA-010957-DCAC-EMI-Filter (L5.5 L5.6 L5.7 L5.8), TIDA-010957-DCAC-Current-Sensing (U5.2)
I_PCC_N+: TIDA-010957-DCAC-EMI-Filter (8 pins), TIDA-010957-DCAC-Current-Sensing (U6.1)
I_PCC_N-: TIDA-010957-DCAC-EMI-Filter (L6.5 L6.6 L6.7 L6.8), TIDA-010957-DCAC-Current-Sensing (U6.2)
I_SENSE_PCC_L1: TIDA-010957-DCAC-CONTROLLER (R21.2), TIDA-010957-DCAC-Current-Sensing (C31.2 R101.2 TP27.1)
I_SENSE_PCC_L2: TIDA-010957-DCAC-CONTROLLER (R32.1), TIDA-010957-DCAC-Current-Sensing (C37.2 R108.2 TP28.1)
I_SENSE_PCC_L3: TIDA-010957-DCAC-CONTROLLER (R20.2), TIDA-010957-DCAC-Current-Sensing (C43.2 R116.2 TP29.1)
I_SENSE_PCC_N: TIDA-010957-DCAC-CONTROLLER (R26.2), TIDA-010957-DCAC-Current-Sensing (C50.2 R125.2 TP30.1)
Middle_Point: TIDA-010957-DCAC-Overview (12 pins), TIDA-010957-DCAC-EMI-Filter (C23.2 C257.2 C258.2)
MONITOR_GaN_ISO_L1: TIDA-010957-DCAC-CONTROLLER (C159.2 R68.2), L1 (R293_L1.1)
MONITOR_GaN_ISO_L2: TIDA-010957-DCAC-CONTROLLER (C160.2 R70.2), L2 (R293_L2.1)
MONITOR_GaN_ISO_L3: TIDA-010957-DCAC-CONTROLLER (C161.2 R72.2), L3 (R293_L3.1)
MONITOR_GaN_ISO_N: TIDA-010957-DCAC-CONTROLLER (C162.2 R73.2), N (R293_N.1)
OC_L1: TIDA-010957-DCAC-CONTROLLER (R62.2), TIDA-010957-DCAC-Current-Sensing (C33.1 R99.1 U2.3)
OC_L2: TIDA-010957-DCAC-CONTROLLER (R64.2), TIDA-010957-DCAC-Current-Sensing (C39.1 R109.1 U4.3)
OC_L3: TIDA-010957-DCAC-CONTROLLER (R66.2), TIDA-010957-DCAC-Current-Sensing (C45.1 R117.1 U5.3)
OC_N: TIDA-010957-DCAC-CONTROLLER (R78.2), TIDA-010957-DCAC-Current-Sensing (C52.1 R123.1 U6.3)
PCC_L1: TIDA-010957-DCAC-Overview (J3.1), TIDA-010957-DCAC-EMI-Filter (F1.2 TP2.1)
PCC_L2: TIDA-010957-DCAC-Overview (J5.1), TIDA-010957-DCAC-EMI-Filter (F2.2 TP3.1)
PCC_L3: TIDA-010957-DCAC-Overview (J7.1), TIDA-010957-DCAC-EMI-Filter (F3.2 TP4.1)
PCC_N: TIDA-010957-DCAC-Overview (J8.1), TIDA-010957-DCAC-EMI-Filter (F4.2 TP7.1)
PWM_S1_GaN_BUF_L1: TIDA-010957-DCAC-PWM-BUFFER (R165.2), L1 (C191_L1.2 R284_L1.2 TP21_L1.1 U28_L1.3)
PWM_S1_GaN_BUF_L2: TIDA-010957-DCAC-PWM-BUFFER (R176.2), L2 (C191_L2.2 R284_L2.2 TP21_L2.1 U28_L2.3)
PWM_S1_GaN_BUF_L3: TIDA-010957-DCAC-PWM-BUFFER (R195.2), L3 (C191_L3.2 R284_L3.2 TP21_L3.1 U28_L3.3)
PWM_S1_GaN_BUF_N: N (C191_N.2 R284_N.2 TP21_N.1 U28_N.3), TIDA-010957-DCAC-PWM-BUFFER (R177.2)
PWM_S1_GaN_L1: TIDA-010957-DCAC-CONTROLLER (R43.1), TIDA-010957-DCAC-PWM-BUFFER (C109.1 R170.2 U15.2)
PWM_S1_GaN_L2: TIDA-010957-DCAC-CONTROLLER (R51.1), TIDA-010957-DCAC-PWM-BUFFER (C116.1 R185.2 U16.2)
PWM_S1_GaN_L3: TIDA-010957-DCAC-CONTROLLER (R44.1), TIDA-010957-DCAC-PWM-BUFFER (C127.1 R200.2 U18.2)
PWM_S1_GaN_N: TIDA-010957-DCAC-CONTROLLER (R52.1), TIDA-010957-DCAC-PWM-BUFFER (C121.1 R190.2 U17.2)
PWM_S2_GaN_BUF_L1: TIDA-010957-DCAC-PWM-BUFFER (R166.2), L1 (C205_L1.2 R295_L1.2 TP22_L1.1 U32_L1.3)
PWM_S2_GaN_BUF_L2: TIDA-010957-DCAC-PWM-BUFFER (R178.2), L2 (C205_L2.2 R295_L2.2 TP22_L2.1 U32_L2.3)
PWM_S2_GaN_BUF_L3: TIDA-010957-DCAC-PWM-BUFFER (R196.2), L3 (C205_L3.2 R295_L3.2 TP22_L3.1 U32_L3.3)
PWM_S2_GaN_BUF_N: N (C205_N.2 R295_N.2 TP22_N.1 U32_N.3), TIDA-010957-DCAC-PWM-BUFFER (R179.2)
PWM_S2_GaN_L1: TIDA-010957-DCAC-CONTROLLER (R47.1), TIDA-010957-DCAC-PWM-BUFFER (C110.1 R171.2 U15.5)
PWM_S2_GaN_L2: TIDA-010957-DCAC-CONTROLLER (R55.1), TIDA-010957-DCAC-PWM-BUFFER (C117.1 R186.2 U16.5)
PWM_S2_GaN_L3: TIDA-010957-DCAC-CONTROLLER (R48.1), TIDA-010957-DCAC-PWM-BUFFER (C128.1 R201.2 U18.5)
PWM_S2_GaN_N: TIDA-010957-DCAC-CONTROLLER (R56.1), TIDA-010957-DCAC-PWM-BUFFER (C122.1 R191.2 U17.5)
PWM_S3_GaN_BUF_L1: TIDA-010957-DCAC-PWM-BUFFER (R167.2), L1 (C231_L1.2 R305_L1.2 TP23_L1.1 U37_L1.3)
PWM_S3_GaN_BUF_L2: TIDA-010957-DCAC-PWM-BUFFER (R180.2), L2 (C231_L2.2 R305_L2.2 TP23_L2.1 U37_L2.3)
PWM_S3_GaN_BUF_L3: TIDA-010957-DCAC-PWM-BUFFER (R197.2), L3 (C231_L3.2 R305_L3.2 TP23_L3.1 U37_L3.3)
PWM_S3_GaN_BUF_N: N (C231_N.2 R305_N.2 TP23_N.1 U37_N.3), TIDA-010957-DCAC-PWM-BUFFER (R181.2)
PWM_S3_GaN_L1: TIDA-010957-DCAC-CONTROLLER (R49.1), TIDA-010957-DCAC-PWM-BUFFER (C111.1 R172.2 U15.9)
PWM_S3_GaN_L2: TIDA-010957-DCAC-CONTROLLER (R57.1), TIDA-010957-DCAC-PWM-BUFFER (C118.1 R187.2 U16.9)
PWM_S3_GaN_L3: TIDA-010957-DCAC-CONTROLLER (R50.1), TIDA-010957-DCAC-PWM-BUFFER (C129.1 R202.2 U18.9)
PWM_S3_GaN_N: TIDA-010957-DCAC-CONTROLLER (R58.1), TIDA-010957-DCAC-PWM-BUFFER (C123.1 R192.2 U17.9)
PWM_S4_GaN_BUF_L1: TIDA-010957-DCAC-PWM-BUFFER (R168.2), L1 (C248_L1.2 R322_L1.2 TP24_L1.1 U43_L1.3)
PWM_S4_GaN_BUF_L2: TIDA-010957-DCAC-PWM-BUFFER (R182.2), L2 (C248_L2.2 R322_L2.2 TP24_L2.1 U43_L2.3)
PWM_S4_GaN_BUF_L3: TIDA-010957-DCAC-PWM-BUFFER (R198.2), L3 (C248_L3.2 R322_L3.2 TP24_L3.1 U43_L3.3)
PWM_S4_GaN_BUF_N: N (C248_N.2 R322_N.2 TP24_N.1 U43_N.3), TIDA-010957-DCAC-PWM-BUFFER (R183.2)
PWM_S4_GaN_L1: TIDA-010957-DCAC-CONTROLLER (R45.1), TIDA-010957-DCAC-PWM-BUFFER (C112.1 R173.2 U15.12)
PWM_S4_GaN_L2: TIDA-010957-DCAC-CONTROLLER (R53.1), TIDA-010957-DCAC-PWM-BUFFER (C119.1 R188.2 U16.12)
PWM_S4_GaN_L3: TIDA-010957-DCAC-CONTROLLER (R46.1), TIDA-010957-DCAC-PWM-BUFFER (C130.1 R203.2 U18.12)
PWM_S4_GaN_N: TIDA-010957-DCAC-CONTROLLER (R54.1), TIDA-010957-DCAC-PWM-BUFFER (C124.1 R193.2 U17.12)
T_HEATSINK_DCAC: TIDA-010957-DCAC-CONTROLLER (R42.1), TIDA-010957-DCAC-Mechanics (C14.1 R19.1)
TEMP_S3_GaN_ISO_L1: TIDA-010957-DCAC-CONTROLLER (C173.2 R74.2), L1 (R302_L1.1)
TEMP_S3_GaN_ISO_L2: TIDA-010957-DCAC-CONTROLLER (C174.2 R75.2), L2 (R302_L2.1)
TEMP_S3_GaN_ISO_L3: TIDA-010957-DCAC-CONTROLLER (C175.2 R76.2), L3 (R302_L3.1)
TEMP_S3_GaN_ISO_N: TIDA-010957-DCAC-CONTROLLER (C176.2 R77.2), N (R302_N.1)
V_FC_L1: TIDA-010957-DCAC-CONTROLLER (R31.2), TIDA-010957-DCAC-FC-OP-AMP (C96.1 R146.2 TP32.1)
V_FC_L2: TIDA-010957-DCAC-CONTROLLER (R22.2), TIDA-010957-DCAC-FC-OP-AMP (C99.1 R151.2 TP33.1)
V_FC_L3: TIDA-010957-DCAC-CONTROLLER (R27.2), TIDA-010957-DCAC-FC-OP-AMP (C102.1 R156.2 TP34.1)
V_FC_N: TIDA-010957-DCAC-CONTROLLER (R24.2), TIDA-010957-DCAC-FC-OP-AMP (C105.1 R161.2 TP35.1)
V_FC_NEG_L1: TIDA-010957-DCAC-FC-OP-AMP (R147.2), L1 (U41_L1.6)
V_FC_NEG_L2: TIDA-010957-DCAC-FC-OP-AMP (R152.2), L2 (U41_L2.6)
V_FC_NEG_L3: TIDA-010957-DCAC-FC-OP-AMP (R157.2), L3 (U41_L3.6)
V_FC_NEG_N: N (U41_N.6), TIDA-010957-DCAC-FC-OP-AMP (R162.2)
V_FC_POS_L1: TIDA-010957-DCAC-FC-OP-AMP (R145.2), L1 (U41_L1.7)
V_FC_POS_L2: TIDA-010957-DCAC-FC-OP-AMP (R150.2), L2 (U41_L2.7)
V_FC_POS_L3: TIDA-010957-DCAC-FC-OP-AMP (R155.2), L3 (U41_L3.7)
V_FC_POS_N: N (U41_N.7), TIDA-010957-DCAC-FC-OP-AMP (R160.2)
V_PCC_L1: TIDA-010957-DCAC-EMI-Filter (C20.2 L12.1 L19.1), TIDA-010957-DCAC-Measurements-Voltages-AC (R236.2)
V_PCC_L2: TIDA-010957-DCAC-EMI-Filter (C21.2 L12.3 L19.3), TIDA-010957-DCAC-Measurements-Voltages-AC (R241.2)
V_PCC_L3: TIDA-010957-DCAC-EMI-Filter (C22.2 L12.5 L19.5), TIDA-010957-DCAC-Measurements-Voltages-AC (R246.2)
V_PCC_N: TIDA-010957-DCAC-EMI-Filter (6 pins), TIDA-010957-DCAC-Measurements-Voltages-AC (25 pins)
V_SENSE_DC: TIDA-010957-DCAC-CONTROLLER (R35.1), TIDA-010957-DCAC-DC-Voltage-Measurements (C84.1 R140.2 TP31.1)
V_SENSE_PCC_L1: TIDA-010957-DCAC-CONTROLLER (R28.2), TIDA-010957-DCAC-Measurements-Voltages-AC (C59.2 R130.2 TP36.1)
V_SENSE_PCC_L2: TIDA-010957-DCAC-CONTROLLER (R33.2), TIDA-010957-DCAC-Measurements-Voltages-AC (C66.2 R132.2 TP37.1)
V_SENSE_PCC_L3: TIDA-010957-DCAC-CONTROLLER (R34.1), TIDA-010957-DCAC-Measurements-Voltages-AC (C73.2 R134.2 TP38.1)

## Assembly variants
001: not fitted C23 C257 C258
